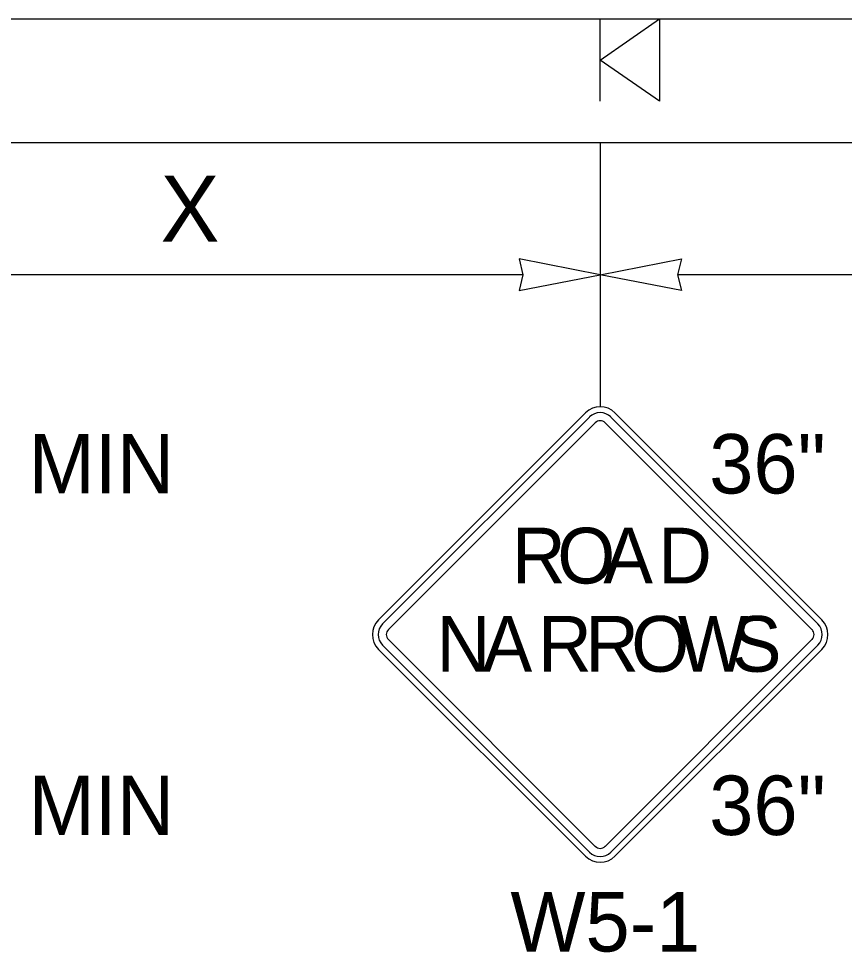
# Model space of a CAD drawing. Extents: x 99999.1 to 100055.7, y 99995 to 100010.7.
# Drawn here: x 100024.071 to 100025.071, y 100004.255 to 100005.386 of the extents above; entities that cross this region are included whole.
import ezdxf

# ---------------------------------------------------------------- set-up
doc = ezdxf.new("R2010")
doc.units = 0
for name, color, linetype in [('RD_ED_ShoulderPavedEdge', 7, 'Continuous'), ('TR_SN_ConstructionSigns', 7, 'Continuous'), ('TR_WZ_PortableSignMountBlk-Org', 7, 'Continuous'), ('TR_WZ_WorkZoneDetails', 7, 'Continuous'), ('TR_WZ_WorkZoneTextCurrent', 7, 'Continuous')]:
    doc.layers.add(name, color=color, linetype=linetype)

msp = doc.modelspace()

# ---------------------------------------------------------------- linework, layer by layer
at = {"layer": 'RD_ED_ShoulderPavedEdge'}
msp.add_line((100020.8283, 100005.2357), (100035.62, 100005.2357), dxfattribs=at)
at = {"layer": 'TR_SN_ConstructionSigns'}
for p, q in [((100024.7574, 100004.9083), (100024.5068, 100004.6577)), ((100024.7624, 100004.9033), (100024.5118, 100004.6528)), ((100025.0388, 100004.6528), (100024.7882, 100004.9033)), ((100025.0438, 100004.6577), (100024.7932, 100004.9083)), ((100024.5187, 100004.6458), (100024.7693, 100004.8964)), ((100024.7812, 100004.8964), (100025.0318, 100004.6458)), ((100024.7693, 100004.3833), (100024.5187, 100004.6339)), ((100025.0318, 100004.6339), (100024.7812, 100004.3833)), ((100024.5068, 100004.6219), (100024.7574, 100004.3714)), ((100024.5118, 100004.6269), (100024.7624, 100004.3763)), ((100024.7882, 100004.3763), (100025.0388, 100004.6269)), ((100024.7932, 100004.3714), (100025.0438, 100004.6219))]:
    msp.add_line(p, q, dxfattribs=at)
for centre, radius, start, end in [((100024.7753, 100004.8904), 0.0253, 45, 135), ((100024.7753, 100004.8904), 0.0183, 45, 135), ((100024.7753, 100004.8904), 0.00844, 45, 135), ((100024.5247, 100004.6398), 0.0253, 135, 225), ((100024.5247, 100004.6398), 0.0183, 135, 225), ((100025.0259, 100004.6398), 0.0183, 315, 45), ((100025.0259, 100004.6398), 0.0253, 315, 45), ((100024.5247, 100004.6398), 0.00844, 135, 225), ((100025.0259, 100004.6398), 0.00844, 315, 45), ((100024.7753, 100004.3893), 0.00844, 225, 315), ((100024.7753, 100004.3893), 0.0253, 225, 315), ((100024.7753, 100004.3893), 0.0183, 225, 315)]:
    msp.add_arc(centre, radius, start, end, dxfattribs=at)
at = {"layer": 'TR_WZ_PortableSignMountBlk-Org'}
msp.add_line((100024.7753, 100005.2858), (100024.7753, 100005.3858), dxfattribs=at)
msp.add_lwpolyline([(100024.7753, 100005.3357), (100024.8471, 100005.3858), (100024.8471, 100005.2858)], close=True, dxfattribs=at)
at = {"layer": 'TR_WZ_WorkZoneDetails'}
for p, q in [((100022.1753, 100005.3858), (100026.6368, 100005.3858)), ((100024.7753, 100005.236), (100024.7753, 100004.9157)), ((100024.6815, 100005.0757), (100023.869, 100005.0757)), ((100025.6815, 100005.0757), (100024.869, 100005.0757))]:
    msp.add_line(p, q, dxfattribs=at)
for points in [[(100024.7753, 100005.0757), (100024.677, 100005.095), (100024.6815, 100005.0757), (100024.677, 100005.0565)], [(100024.7753, 100005.0757), (100024.8736, 100005.095), (100024.869, 100005.0757), (100024.8736, 100005.0565)]]:
    msp.add_lwpolyline(points, close=True, dxfattribs=at)

# ---------------------------------------------------------------- texts
at = {"layer": 'TR_SN_ConstructionSigns'}
for s, p in [('MIN', (100024.0829, 100004.8107)), ('36"', (100024.9073, 100004.8107)), ('MIN', (100024.0829, 100004.397)), ('36"', (100024.9073, 100004.397)), ('W5-1', (100024.6666, 100004.2559))]:
    msp.add_text(s, height=0.072, rotation=360, dxfattribs=at).set_placement(p)
for s, p in [('R', (100024.6684, 100004.7017)), ('O', (100024.7233, 100004.7017)), ('A', (100024.779, 100004.7017)), ('D', (100024.8454, 100004.7017)), ('O', (100024.8129, 100004.5948)), ('S', (100024.9347, 100004.5948)), ('N', (100024.577, 100004.5948)), ('A', (100024.6328, 100004.5948)), ('R', (100024.7, 100004.5948)), ('R', (100024.7571, 100004.5948)), ('W', (100024.8694, 100004.5948))]:
    msp.add_text(s, height=0.0675, dxfattribs=at).set_placement(p)
at = {"layer": 'TR_WZ_WorkZoneTextCurrent'}
msp.add_text('X', height=0.08, rotation=360, dxfattribs=at).set_placement((100024.2428, 100005.1157))

doc.saveas('drawing.dxf')
